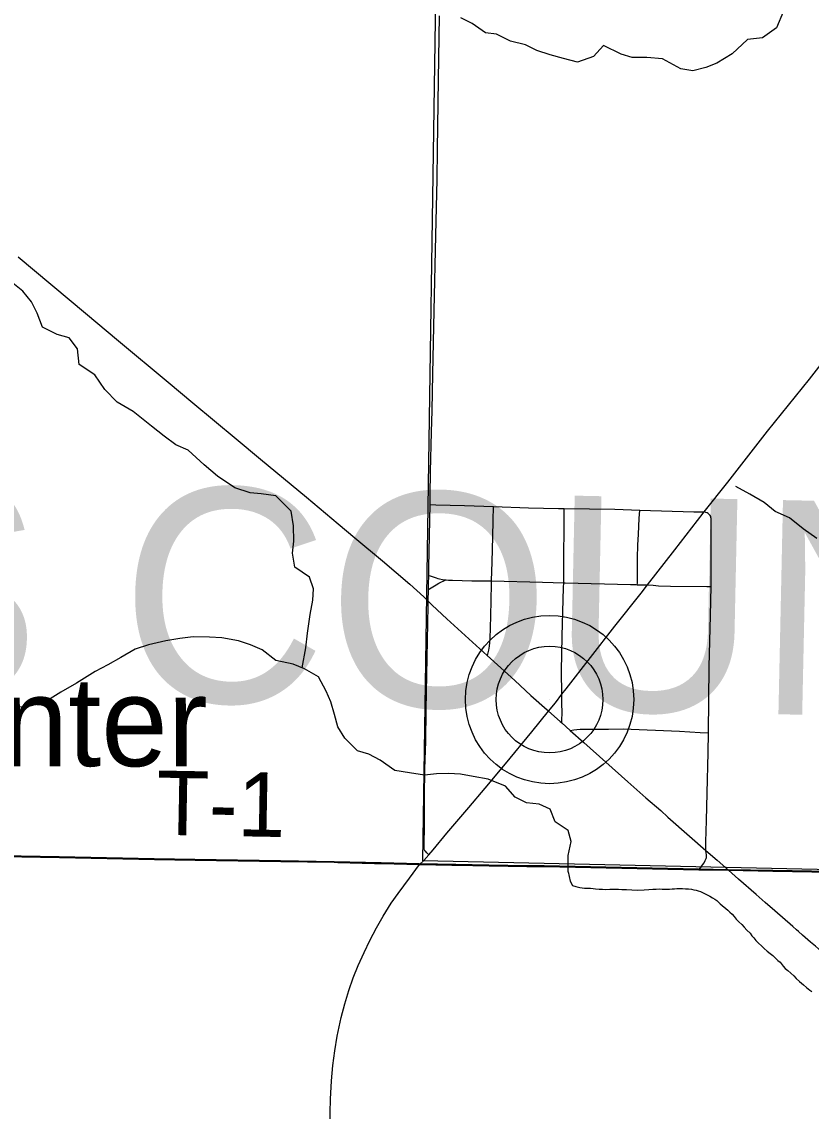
# Model space of a CAD drawing. Extents: x 0 to 34, y 0 to 22.
# Drawn here: x 4.291 to 4.989, y 16.256 to 17.219 of the extents above; entities that cross this region are included whole.
import ezdxf

# ---------------------------------------------------------------- set-up
doc = ezdxf.new("R2010")
doc.units = 0
for name, color, linetype in [('GM_X_County_Road', 7, 'Continuous'), ('GM_X_County_Text', 7, 'Continuous'), ('GM_X_Minor_River', 7, 'Continuous'), ('GM_X_Section', 7, 'Continuous'), ('GM_X_State_Route', 7, 'Continuous'), ('GM_X_Township_Road', 7, 'Continuous'), ('GM_X_Township_Road_Text', 7, 'Continuous'), ('GM_X_Unincorporated', 7, 'Continuous'), ('GM_X_Unincorporated_Location', 7, 'Continuous'), ('GM_X_Unincorporated_Text', 7, 'Continuous'), ('SH_Cut_Line', 7, 'Continuous')]:
    doc.layers.add(name, color=color, linetype=linetype)

msp = doc.modelspace()

# ---------------------------------------------------------------- linework, layer by layer
at = {"layer": 'GM_X_County_Road'}
for p, q in [((4.76822, 16.59908), (4.77563, 16.59246)), ((4.64233, 16.4738), (4.67093, 16.47328)), ((4.67093, 16.47328), (4.67192, 16.47326)), ((4.88939, 16.4693), (4.91549, 16.46876))]:
    msp.add_line(p, q, dxfattribs=at)
for points in [[(4.28759, 17.01126), (4.34717, 16.96136), (4.37624, 16.93701), (4.4201, 16.90031), (4.44206, 16.882), (4.4803, 16.8502), (4.50187, 16.83239), (4.5425, 16.79861), (4.57057, 16.775), (4.58532, 16.7626), (4.60965, 16.74227), (4.63386, 16.72184), (4.64629, 16.71066), (4.6502, 16.70664)], [(4.6502, 16.70664), (4.65365, 16.70309), (4.66644, 16.69125), (4.70226, 16.65869)], [(4.70226, 16.65869), (4.70508, 16.65612), (4.72668, 16.63645), (4.74086, 16.6234), (4.75515, 16.61054), (4.75648, 16.60937)], [(4.76822, 16.59908), (4.7683, 16.6003), (4.7684, 16.60905), (4.76827, 16.61543), (4.76829, 16.61757), (4.76835, 16.62443)], [(4.75648, 16.60937), (4.76684, 16.60031), (4.76822, 16.59908)], [(4.77563, 16.59246), (4.7877, 16.58169), (4.82656, 16.54689), (4.84247, 16.53298), (4.8556, 16.52159), (4.86198, 16.5157), (4.88107, 16.49883), (4.89552, 16.48623)], [(4.88939, 16.4693), (4.89096, 16.47131), (4.89206, 16.47271), (4.89287, 16.4738), (4.89396, 16.47539), (4.89504, 16.47741), (4.89576, 16.47917), (4.89598, 16.48011), (4.89609, 16.48108), (4.89604, 16.48256), (4.89586, 16.48427), (4.89552, 16.48623)], [(4.89552, 16.48623), (4.90545, 16.47759), (4.91549, 16.46876)], [(4.67192, 16.47326), (4.67488, 16.47321), (4.70389, 16.47271), (4.7374, 16.47222), (4.75292, 16.47218), (4.88939, 16.4693)], [(5.16387, 16.2526), (5.14863, 16.2654), (5.13162, 16.27996), (5.09455, 16.31218), (5.08236, 16.3228), (5.07108, 16.33257), (5.05935, 16.34276), (5.04292, 16.35702), (5.03823, 16.36112), (5.02892, 16.36938), (5.0122, 16.38421), (5.00577, 16.39), (5.00029, 16.39473), (4.99233, 16.40162), (4.98814, 16.40529), (4.98107, 16.41134), (4.97735, 16.41462), (4.97552, 16.41625), (4.97227, 16.41912), (4.95637, 16.43301), (4.94792, 16.44035), (4.93994, 16.44727), (4.92452, 16.46082), (4.91549, 16.46876)], [(4.91549, 16.46876), (4.95484, 16.46793), (5.00655, 16.46706)]]:
    msp.add_lwpolyline(points, dxfattribs=at)
at = {"layer": 'GM_X_County_Text'}
for points in [[(4.25675, 16.48176), (4.32389, 16.48079), (4.40778, 16.47895), (4.44382, 16.47831), (4.51966, 16.4771), (4.56687, 16.47639), (4.60854, 16.47525), (4.64209, 16.47436), (4.67464, 16.47376), (4.70365, 16.47326), (4.73717, 16.47278), (4.75269, 16.47273), (4.88915, 16.46986), (4.91525, 16.46931), (4.9546, 16.46848), (5.07394, 16.46648)], [(5.07394, 16.46648), (4.9546, 16.46848), (4.91525, 16.46931), (4.88915, 16.46986), (4.75269, 16.47273), (4.73717, 16.47278), (4.70365, 16.47326), (4.67464, 16.47376), (4.64209, 16.47436), (4.60854, 16.47525), (4.56687, 16.47639), (4.51966, 16.4771), (4.44382, 16.47831), (4.40778, 16.47895), (4.32389, 16.48079), (4.25675, 16.48176)]]:
    msp.add_lwpolyline(points, dxfattribs=at)
at = {"layer": 'GM_X_Minor_River'}
for points in [[(4.96422, 17.22843), (4.95787, 17.21377), (4.94557, 17.20491), (4.93226, 17.20327), (4.91875, 17.19064), (4.90532, 17.18256), (4.89539, 17.17858), (4.88395, 17.17577), (4.87337, 17.17749), (4.85723, 17.18614), (4.84323, 17.18755), (4.83033, 17.18742), (4.82053, 17.19026), (4.80513, 17.19814), (4.79622, 17.18846), (4.7821, 17.18342), (4.76965, 17.1867), (4.75795, 17.18995), (4.74627, 17.19359), (4.73613, 17.19872), (4.72292, 17.20201), (4.71052, 17.20793), (4.70069, 17.20926), (4.68909, 17.21745), (4.67895, 17.22257)], [(4.53861, 16.64788), (4.54193, 16.66557), (4.54332, 16.67843), (4.54591, 16.69507), (4.54805, 16.70754), (4.54863, 16.71777), (4.54503, 16.72808), (4.53231, 16.73667), (4.53027, 16.74922), (4.53124, 16.75982), (4.53112, 16.77347), (4.5291, 16.78641), (4.51533, 16.79994), (4.50247, 16.80171), (4.49263, 16.80266), (4.47906, 16.80709), (4.46371, 16.81725), (4.45215, 16.82733), (4.43798, 16.84012), (4.42708, 16.84488), (4.41661, 16.85266), (4.40541, 16.8616), (4.38935, 16.87442), (4.3751, 16.88266), (4.36432, 16.89387), (4.35547, 16.90693), (4.34161, 16.91592), (4.33999, 16.92998), (4.33259, 16.9396), (4.32203, 16.94246), (4.30926, 16.94915), (4.30457, 16.96138), (4.29945, 16.97133), (4.29168, 16.98096), (4.27861, 16.99145)], [(4.99353, 16.76224), (4.98156, 16.77082), (4.96961, 16.78053), (4.95683, 16.78609), (4.94712, 16.79386), (4.93437, 16.80131), (4.92198, 16.808)], [(4.77369, 16.46716), (4.77379, 16.48194), (4.77639, 16.49416), (4.77393, 16.50407), (4.76231, 16.5115), (4.75798, 16.52296), (4.74821, 16.52732), (4.73685, 16.5283), (4.72709, 16.53342), (4.71855, 16.54307), (4.70313, 16.54943), (4.6899, 16.55159), (4.67857, 16.5537), (4.66796, 16.55429), (4.65734, 16.55411), (4.64669, 16.5528), (4.63346, 16.55495), (4.62061, 16.5571), (4.60751, 16.56607), (4.59776, 16.57157), (4.58758, 16.57442), (4.57642, 16.58564), (4.57016, 16.59562), (4.56734, 16.60667), (4.56414, 16.61773), (4.55978, 16.6273), (4.55319, 16.63994), (4.54082, 16.64701), (4.53065, 16.65099), (4.51555, 16.65432), (4.50322, 16.66366), (4.49306, 16.66803), (4.48252, 16.67165), (4.46778, 16.67421), (4.45679, 16.6748), (4.44239, 16.67508), (4.43061, 16.67379), (4.41805, 16.67176), (4.40282, 16.66826), (4.39099, 16.66431), (4.37833, 16.65698), (4.36683, 16.65037), (4.35572, 16.64452), (4.33922, 16.63422), (4.32541, 16.62614), (4.31582, 16.62026), (4.30549, 16.61591), (4.29597, 16.61344), (4.28269, 16.61294)], [(4.77382, 16.46756), (4.77547, 16.4591), (4.77766, 16.45525), (4.78068, 16.45442), (4.78407, 16.45358), (4.78634, 16.45315), (4.78824, 16.4531), (4.79127, 16.45303), (4.79355, 16.45298), (4.79582, 16.45255), (4.79809, 16.45249), (4.80112, 16.45204), (4.80415, 16.45197), (4.80719, 16.4519), (4.81062, 16.45219), (4.81403, 16.45211), (4.8182, 16.45202), (4.82124, 16.45194), (4.82541, 16.45184), (4.82996, 16.45136), (4.83527, 16.45123), (4.84097, 16.45148), (4.84515, 16.45176), (4.84858, 16.45206), (4.85161, 16.45198), (4.85428, 16.4523), (4.85693, 16.45224), (4.85959, 16.45217), (4.86338, 16.45209), (4.86567, 16.45241), (4.86794, 16.45236), (4.86985, 16.45269), (4.87213, 16.45264), (4.87478, 16.45258), (4.87744, 16.45251), (4.8801, 16.45245), (4.88274, 16.45201), (4.88501, 16.45157), (4.8869, 16.45115), (4.88879, 16.45072), (4.89067, 16.44992), (4.89255, 16.44912), (4.89442, 16.44831), (4.89668, 16.44712), (4.89893, 16.44593), (4.90154, 16.44434), (4.90342, 16.44316), (4.90529, 16.44198), (4.90826, 16.43925), (4.91496, 16.43339), (4.91682, 16.43183), (4.91867, 16.42989), (4.92052, 16.42795), (4.92237, 16.42562), (4.92459, 16.42329), (4.92719, 16.42095), (4.92941, 16.41862), (4.93163, 16.41591), (4.9346, 16.41318), (4.93607, 16.41086), (4.93792, 16.40892), (4.93976, 16.4066), (4.94198, 16.40427), (4.94459, 16.40193), (4.94719, 16.39959), (4.94979, 16.39725), (4.9524, 16.39529), (4.95464, 16.39333), (4.95687, 16.39138), (4.95909, 16.38905), (4.96133, 16.38748), (4.96391, 16.384), (4.96576, 16.38206), (4.96799, 16.3801), (4.9706, 16.37776), (4.9732, 16.37542), (4.97542, 16.37309), (4.97839, 16.37036), (4.98175, 16.36762), (4.98435, 16.36528), (4.98733, 16.36293), (4.9892, 16.36175)]]:
    msp.add_lwpolyline(points, dxfattribs=at)
at = {"layer": 'GM_X_Section'}
msp.add_lwpolyline([(4.66052, 17.47484), (5.65514, 17.45551), (5.64591, 16.45512), (5.62401, 16.4556), (4.6453, 16.47708)], close=True, dxfattribs=at)
at = {"layer": 'GM_X_State_Route'}
for points in [[(4.65172, 16.79222), (4.65185, 16.80035), (4.65226, 16.82132), (4.653, 16.85605), (4.65347, 16.87531), (4.65433, 16.90762), (4.65536, 16.96357), (4.65678, 17.03006), (4.6579, 17.07976), (4.6582, 17.10588), (4.65928, 17.16795), (4.65999, 17.22429)], [(4.65079, 16.48238), (4.65437, 16.48681), (4.66665, 16.50167), (4.68593, 16.52443), (4.70047, 16.54145), (4.71842, 16.56294), (4.74175, 16.59125), (4.75648, 16.60937), (4.76256, 16.61683), (4.76835, 16.62443), (4.77199, 16.6292), (4.8151, 16.68466), (4.83826, 16.71391), (4.84392, 16.7212), (4.86803, 16.75221), (4.89323, 16.78459), (4.89404, 16.78561), (4.91487, 16.81187), (4.95013, 16.85691), (4.98702, 16.90306), (5.02455, 16.95107)], [(4.65079, 16.48238), (4.64882, 16.48435), (4.64762, 16.48555), (4.64715, 16.48608), (4.64665, 16.48705), (4.64648, 16.48775), (4.64639, 16.48872), (4.64676, 16.51071), (4.64695, 16.53303), (4.64727, 16.5585), (4.64789, 16.58274), (4.64838, 16.61068), (4.65012, 16.70258), (4.6502, 16.70664), (4.65039, 16.71711), (4.65048, 16.72179), (4.65063, 16.72937), (4.65078, 16.73672), (4.65172, 16.79222)], [(4.64233, 16.4738), (4.64637, 16.47754), (4.65079, 16.48238)], [(4.56235, 16.20732), (4.56369, 16.26638), (4.56451, 16.28255), (4.56578, 16.2962), (4.56751, 16.30918), (4.56976, 16.32208), (4.57329, 16.33852), (4.57639, 16.3506), (4.57998, 16.36255), (4.58392, 16.37373), (4.58831, 16.38473), (4.59336, 16.39613), (4.59856, 16.40678), (4.60445, 16.41777), (4.61028, 16.42821), (4.61735, 16.43957), (4.62342, 16.44812), (4.63361, 16.46179), (4.64233, 16.4738)]]:
    msp.add_lwpolyline(points, dxfattribs=at)
at = {"layer": 'GM_X_Township_Road'}
for p, q in [((4.57016, 16.47575), (4.60268, 16.47486)), ((4.64233, 16.4738), (4.67093, 16.47328)), ((4.67093, 16.47328), (4.67192, 16.47326)), ((4.88939, 16.4693), (4.91549, 16.46876))]:
    msp.add_line(p, q, dxfattribs=at)
for points in [[(4.65172, 16.79222), (4.65685, 16.79206), (4.68232, 16.79124), (4.70791, 16.79038)], [(4.70609, 16.72458), (4.70656, 16.74159), (4.70716, 16.76349), (4.70757, 16.77811), (4.70791, 16.79038)], [(4.70791, 16.79038), (4.73869, 16.78935), (4.76533, 16.7886), (4.77043, 16.78853)], [(4.76987, 16.72295), (4.77011, 16.74565), (4.77038, 16.77215), (4.77043, 16.78853)], [(4.77043, 16.78853), (4.81494, 16.78796), (4.83714, 16.7873)], [(4.83495, 16.7213), (4.83498, 16.72309), (4.83523, 16.74509), (4.83553, 16.75613), (4.83601, 16.76585), (4.83662, 16.77991), (4.83714, 16.7873)], [(4.83714, 16.7873), (4.88501, 16.78587), (4.89404, 16.78561)], [(4.90029, 16.71969), (4.90034, 16.77681), (4.90034, 16.77883), (4.90026, 16.77978), (4.90005, 16.78077), (4.89983, 16.78157), (4.89937, 16.78251), (4.89821, 16.78375), (4.89749, 16.78428), (4.89657, 16.78482), (4.89553, 16.78521), (4.89404, 16.78561)], [(4.65039, 16.71711), (4.65114, 16.71757), (4.65415, 16.71946), (4.65704, 16.72128), (4.65945, 16.72268), (4.66184, 16.72382), (4.66346, 16.72449), (4.66445, 16.72491), (4.66588, 16.72551)], [(4.65063, 16.72937), (4.65172, 16.72901), (4.6544, 16.72813), (4.65707, 16.72726), (4.65855, 16.72682), (4.66022, 16.72639), (4.66267, 16.72584), (4.66588, 16.72551)], [(4.66588, 16.72551), (4.66808, 16.72535), (4.67149, 16.72525), (4.68855, 16.72483), (4.70273, 16.72466), (4.70609, 16.72458)], [(4.70226, 16.65869), (4.7028, 16.65982), (4.70381, 16.66337), (4.70431, 16.66702), (4.70488, 16.67353), (4.70537, 16.69334), (4.70601, 16.72179), (4.70609, 16.72458)], [(4.70609, 16.72458), (4.75122, 16.72349), (4.76987, 16.72295)], [(4.76835, 16.62443), (4.76796, 16.64495), (4.76846, 16.67592), (4.76971, 16.71872), (4.76987, 16.72295)], [(4.76987, 16.72295), (4.77111, 16.72292), (4.82893, 16.72159), (4.83372, 16.7214), (4.83495, 16.7213)], [(4.83495, 16.7213), (4.84138, 16.72123), (4.84392, 16.7212)], [(4.84392, 16.7212), (4.84882, 16.72075), (4.85355, 16.72038), (4.86424, 16.72008), (4.89637, 16.71964), (4.90029, 16.71969)], [(4.8978, 16.59024), (4.89842, 16.64874), (4.89967, 16.694), (4.90029, 16.71969)], [(4.77563, 16.59246), (4.77887, 16.59298), (4.78142, 16.59332), (4.78448, 16.59358), (4.78891, 16.59368), (4.79897, 16.59362), (4.80948, 16.59367), (4.82249, 16.59375), (4.87209, 16.59191), (4.89058, 16.59071), (4.8978, 16.59024)], [(4.89552, 16.48623), (4.89551, 16.48827), (4.89548, 16.49409), (4.89612, 16.51271), (4.89665, 16.53694), (4.89761, 16.57296), (4.8978, 16.59024)], [(3.64509, 16.49442), (3.64942, 16.49431), (3.72121, 16.4924), (3.84303, 16.48946), (3.91637, 16.48788), (4.0127, 16.48589), (4.11154, 16.48424), (4.17681, 16.4831), (4.25698, 16.4812), (4.32412, 16.48023), (4.40802, 16.47839), (4.44406, 16.47775), (4.5199, 16.47654), (4.56711, 16.47583), (4.57016, 16.47575)], [(4.60268, 16.47486), (4.60878, 16.47469), (4.64233, 16.4738)], [(4.67192, 16.47326), (4.67488, 16.47321), (4.70389, 16.47271), (4.7374, 16.47222), (4.75292, 16.47218), (4.88939, 16.4693)], [(4.91549, 16.46876), (4.95484, 16.46793), (5.00655, 16.46706)]]:
    msp.add_lwpolyline(points, dxfattribs=at)
at = {"layer": 'GM_X_Unincorporated'}
for radius in [0.0744, 0.04716]:
    msp.add_circle((4.75738, 16.61974), radius, dxfattribs=at)
at = {"layer": 'GM_X_Unincorporated_Location'}
msp.add_line((4.75738, 16.61974), (4.75738, 16.61974), dxfattribs=at)
at = {"layer": 'SH_Cut_Line'}
for points in [[(5.07394, 16.46648), (4.9546, 16.46848), (4.91525, 16.46931), (4.88915, 16.46986), (4.75269, 16.47273), (4.73717, 16.47278), (4.70365, 16.47326), (4.67464, 16.47376), (4.64209, 16.47436), (4.60854, 16.47525), (4.56687, 16.47639), (4.51966, 16.4771), (4.44382, 16.47831), (4.40778, 16.47895), (4.32389, 16.48079), (4.25675, 16.48176)], [(4.25675, 16.48176), (4.32389, 16.48079), (4.40778, 16.47895), (4.44382, 16.47831), (4.51966, 16.4771), (4.56687, 16.47639), (4.60854, 16.47525), (4.64209, 16.47436), (4.67464, 16.47376), (4.70365, 16.47326), (4.73717, 16.47278), (4.75269, 16.47273), (4.88915, 16.46986), (4.91525, 16.46931), (4.9546, 16.46848), (5.07394, 16.46648)]]:
    msp.add_lwpolyline(points, dxfattribs=at)

# ---------------------------------------------------------------- texts
at = {"layer": 'GM_X_County_Text'}
msp.add_text('WILLIAMS COUNTY', height=0.1893939, rotation=358.77482, dxfattribs=at).set_placement((3.09586, 16.64661))
at = {"layer": 'GM_X_Township_Road_Text'}
msp.add_text('T-1', height=0.056818, rotation=358.94319, dxfattribs=at).set_placement((4.40951, 16.50023))
at = {"layer": 'GM_X_Unincorporated_Text'}
msp.add_text('Williams Center', height=0.0789773, rotation=0.00001, dxfattribs=at).set_placement((3.71566, 16.56082))

doc.saveas('drawing.dxf')
